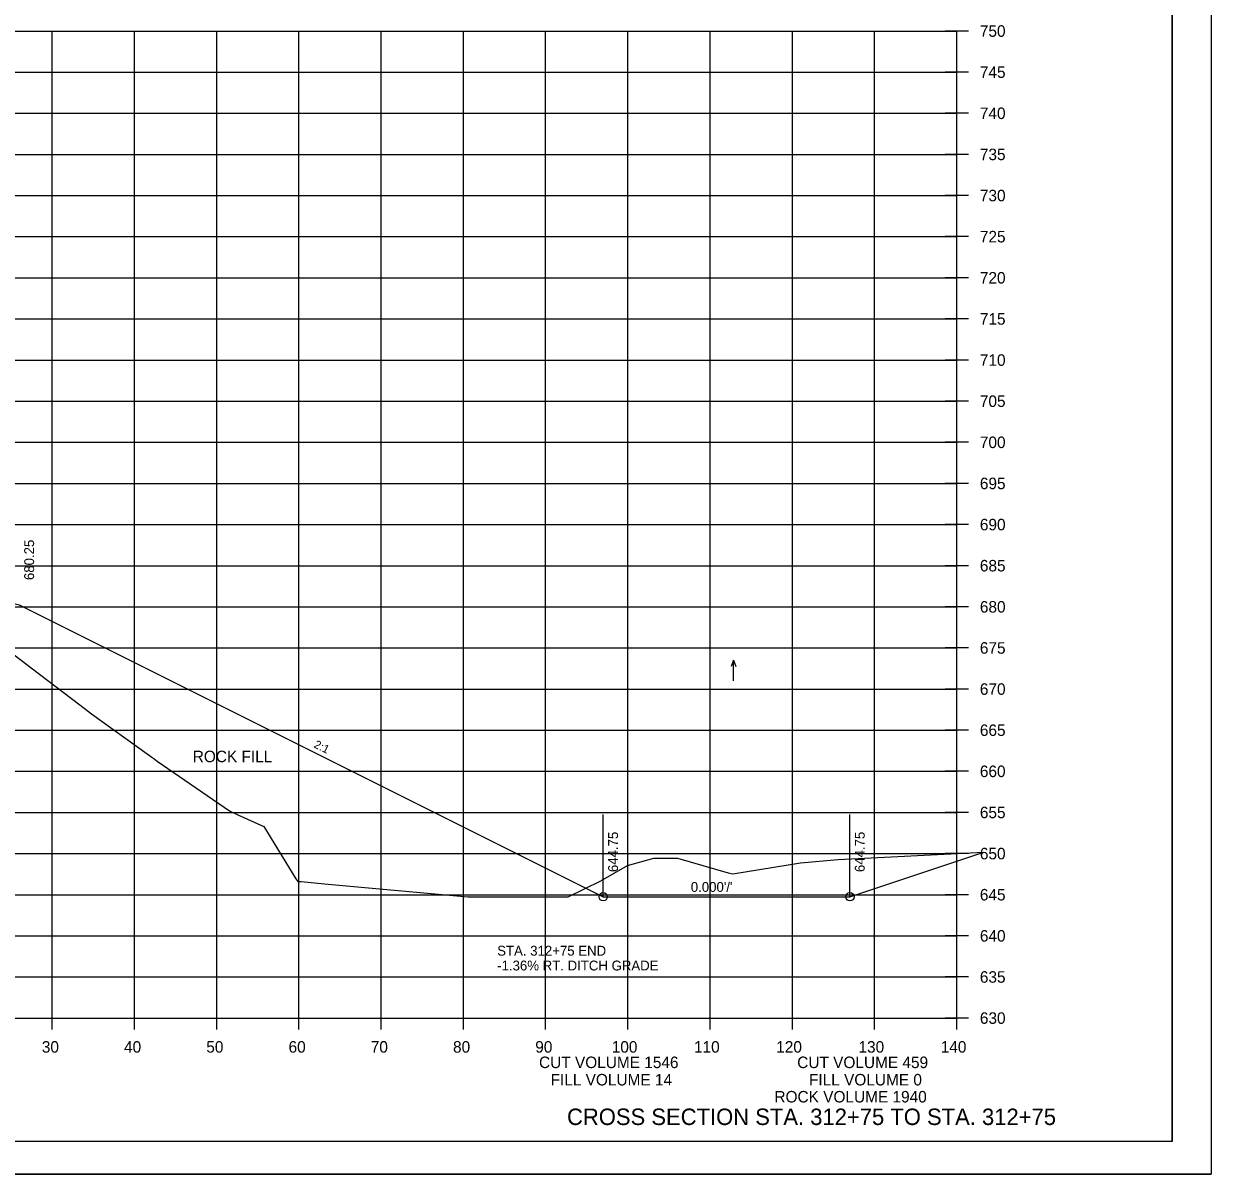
# Model space of a CAD drawing. Extents: x 1370515 to 1370849, y 383299 to 386073.
# Drawn here: x 1370704.3 to 1370848.7, y 385432.8 to 385572.7 of the extents above; entities that cross this region are included whole.
import ezdxf

# ---------------------------------------------------------------- set-up
doc = ezdxf.new("R2010")
doc.units = 0
for name, color, linetype in [('R_Axis', 7, 'Continuous'), ('R_Axis Annot', 7, 'Continuous'), ('R_Border', 7, 'Continuous'), ('R_Draft', 7, 'Continuous'), ('R_Drive', 7, 'Continuous'), ('R_Exist Surface', 7, 'Continuous'), ('R_Fin Surface', 7, 'Continuous'), ('R_Grid', 7, 'Continuous'), ('R_No Plot', 7, 'Continuous'), ('R_Water Annot', 7, 'Continuous'), ('R_Xsect Elev', 7, 'Continuous'), ('R_Xsect Slope', 7, 'Continuous')]:
    doc.layers.add(name, color=color, linetype=linetype)

msp = doc.modelspace()

# ---------------------------------------------------------------- linework, layer by layer
at = {"layer": 'R_Axis'}
for p, q in [((1370819.2, 385571.79), (1370816.4, 385571.79)), ((1370817.8, 385451.79), (1370817.8, 385571.79)), ((1370819.2, 385566.79), (1370816.4, 385566.79)), ((1370819.2, 385561.79), (1370816.4, 385561.79)), ((1370819.2, 385556.79), (1370816.4, 385556.79)), ((1370819.2, 385551.79), (1370816.4, 385551.79)), ((1370819.2, 385546.79), (1370816.4, 385546.79)), ((1370819.2, 385541.79), (1370816.4, 385541.79)), ((1370819.2, 385536.79), (1370816.4, 385536.79)), ((1370819.2, 385531.79), (1370816.4, 385531.79)), ((1370819.2, 385526.79), (1370816.4, 385526.79)), ((1370819.2, 385521.79), (1370816.4, 385521.79)), ((1370819.2, 385516.79), (1370816.4, 385516.79)), ((1370819.2, 385511.79), (1370816.4, 385511.79)), ((1370819.2, 385506.79), (1370816.4, 385506.79)), ((1370819.2, 385501.79), (1370816.4, 385501.79)), ((1370819.2, 385496.79), (1370816.4, 385496.79)), ((1370819.2, 385491.79), (1370816.4, 385491.79)), ((1370819.2, 385486.79), (1370816.4, 385486.79)), ((1370819.2, 385481.79), (1370816.4, 385481.79)), ((1370819.2, 385476.79), (1370816.4, 385476.79)), ((1370819.2, 385471.79), (1370816.4, 385471.79)), ((1370819.2, 385466.79), (1370816.4, 385466.79)), ((1370819.2, 385461.79), (1370816.4, 385461.79)), ((1370819.2, 385456.79), (1370816.4, 385456.79)), ((1370707.8, 385450.39), (1370707.8, 385453.19)), ((1370717.8, 385450.39), (1370717.8, 385453.19)), ((1370727.8, 385450.39), (1370727.8, 385453.19)), ((1370737.8, 385450.39), (1370737.8, 385453.19)), ((1370747.8, 385450.39), (1370747.8, 385453.19)), ((1370757.8, 385450.39), (1370757.8, 385453.19)), ((1370767.8, 385450.39), (1370767.8, 385453.19)), ((1370777.8, 385450.39), (1370777.8, 385453.19)), ((1370787.8, 385450.39), (1370787.8, 385453.19)), ((1370797.8, 385450.39), (1370797.8, 385453.19)), ((1370807.8, 385450.39), (1370807.8, 385453.19)), ((1370817.8, 385450.39), (1370817.8, 385453.19)), ((1370537.8, 385451.79), (1370817.8, 385451.79)), ((1370819.2, 385451.79), (1370816.4, 385451.79))]:
    msp.add_line(p, q, dxfattribs=at)
at = {"layer": 'R_Border'}
for q in [(1370843.98, 385642.25), (1370527.8, 385436.79)]:
    msp.add_line((1370843.98, 385436.79), q, dxfattribs=at)
at = {"layer": 'R_Exist Surface'}
msp.add_lwpolyline([(1370695.72, 385501.64), (1370705.26, 385494.38), (1370711.15, 385489.86), (1370712.6, 385488.77), (1370719.33, 385483.93), (1370719.92, 385483.5), (1370720.01, 385483.43), (1370720.16, 385483.33), (1370720.58, 385483.04), (1370729.35, 385476.99), (1370730.39, 385476.52), (1370733.54, 385475.07), (1370737.44, 385468.73), (1370737.67, 385468.41), (1370738.06, 385468.38), (1370740.92, 385468.12), (1370758.36, 385466.53), (1370760.29, 385466.54), (1370770.53, 385466.54), (1370774.53, 385468.49), (1370777.75, 385470.33), (1370780.95, 385471.22), (1370783.83, 385471.25), (1370790, 385469.46), (1370790.58, 385469.31), (1370798.77, 385470.65), (1370803.35, 385471.09), (1370821.08, 385471.96)], dxfattribs=at)
at = {"layer": 'R_Fin Surface'}
msp.add_lwpolyline([(1370554.83, 385551.11), (1370629.47, 385513.79), (1370634.47, 385513.79), (1370637.83, 385500.34), (1370647.83, 385500.34), (1370651.8, 385501.66), (1370652.52, 385501.84), (1370657.8, 385503.16), (1370665.8, 385503.48), (1370677.8, 385503.72), (1370689.8, 385503.61), (1370697.8, 385503.54), (1370703.8, 385502.04), (1370774.8, 385466.54), (1370804.8, 385466.54), (1370821.08, 385471.96)], dxfattribs=at)
at = {"layer": 'R_Grid'}
for p, q in [((1370537.8, 385571.79), (1370817.8, 385571.79)), ((1370707.8, 385451.79), (1370707.8, 385571.79)), ((1370717.8, 385451.79), (1370717.8, 385571.79)), ((1370727.8, 385451.79), (1370727.8, 385571.79)), ((1370737.8, 385451.79), (1370737.8, 385571.79)), ((1370747.8, 385451.79), (1370747.8, 385571.79)), ((1370757.8, 385451.79), (1370757.8, 385571.79)), ((1370767.8, 385451.79), (1370767.8, 385571.79)), ((1370777.8, 385451.79), (1370777.8, 385571.79)), ((1370787.8, 385451.79), (1370787.8, 385571.79)), ((1370797.8, 385451.79), (1370797.8, 385571.79)), ((1370807.8, 385451.79), (1370807.8, 385571.79)), ((1370817.8, 385451.79), (1370817.8, 385571.79)), ((1370537.8, 385566.79), (1370817.8, 385566.79)), ((1370537.8, 385561.79), (1370817.8, 385561.79)), ((1370537.8, 385556.79), (1370817.8, 385556.79)), ((1370537.8, 385551.79), (1370817.8, 385551.79)), ((1370537.8, 385546.79), (1370817.8, 385546.79)), ((1370537.8, 385541.79), (1370817.8, 385541.79)), ((1370537.8, 385536.79), (1370817.8, 385536.79)), ((1370537.8, 385531.79), (1370817.8, 385531.79)), ((1370537.8, 385526.79), (1370817.8, 385526.79)), ((1370537.8, 385521.79), (1370817.8, 385521.79)), ((1370537.8, 385516.79), (1370817.8, 385516.79)), ((1370537.8, 385511.79), (1370817.8, 385511.79)), ((1370537.8, 385506.79), (1370817.8, 385506.79)), ((1370537.8, 385501.79), (1370817.8, 385501.79)), ((1370537.8, 385496.79), (1370817.8, 385496.79)), ((1370537.8, 385491.79), (1370817.8, 385491.79)), ((1370537.8, 385486.79), (1370817.8, 385486.79)), ((1370537.8, 385481.79), (1370817.8, 385481.79)), ((1370537.8, 385476.79), (1370817.8, 385476.79)), ((1370537.8, 385471.79), (1370817.8, 385471.79)), ((1370537.8, 385466.79), (1370817.8, 385466.79)), ((1370537.8, 385461.79), (1370817.8, 385461.79)), ((1370537.8, 385456.79), (1370817.8, 385456.79)), ((1370537.8, 385451.79), (1370817.8, 385451.79))]:
    msp.add_line(p, q, dxfattribs=at)
at = {"layer": 'R_No Plot'}
msp.add_line((1370515.4, 385432.81), (1370848.73, 385432.81), dxfattribs=at)
for points in [[(1370515.39, 385646.14), (1370848.73, 385646.14), (1370848.73, 385432.81), (1370515.39, 385432.81)], [(1370761.72, 385642.25), (1370761.72, 385632.37), (1370797.45, 385632.37), (1370797.45, 385629.45), (1370820.65, 385629.45), (1370820.65, 385606.23), (1370843.98, 385606.23), (1370843.98, 385436.79), (1370527.8, 385436.79), (1370527.8, 385642.25)]]:
    msp.add_lwpolyline(points, close=True, dxfattribs=at)
for centre in [(1370774.8, 385466.54), (1370774.8, 385466.54), (1370804.8, 385466.54)]:
    msp.add_circle(centre, 0.5, dxfattribs=at)
at = {"layer": 'R_Water Annot'}
for p, q in [((1370790.65, 385495.32), (1370790.37, 385494.55)), ((1370790.65, 385492.8), (1370790.65, 385495.32)), ((1370790.65, 385495.32), (1370790.93, 385494.55))]:
    msp.add_line(p, q, dxfattribs=at)
at = {"layer": 'R_Xsect Elev'}
for p, q in [((1370774.8, 385466.54), (1370774.8, 385476.54)), ((1370804.8, 385466.54), (1370804.8, 385476.54))]:
    msp.add_line(p, q, dxfattribs=at)

# ---------------------------------------------------------------- texts
at = {"layer": 'R_Axis Annot'}
for s, p in [('750', (1370820.6, 385571.09)), ('745', (1370820.6, 385566.09)), ('740', (1370820.6, 385561.09)), ('735', (1370820.6, 385556.09)), ('730', (1370820.6, 385551.09)), ('725', (1370820.6, 385546.09)), ('720', (1370820.6, 385541.09)), ('715', (1370820.6, 385536.09)), ('710', (1370820.6, 385531.09)), ('705', (1370820.6, 385526.09)), ('700', (1370820.6, 385521.09)), ('695', (1370820.6, 385516.09)), ('690', (1370820.6, 385511.09)), ('685', (1370820.6, 385506.09)), ('680', (1370820.6, 385501.09)), ('675', (1370820.6, 385496.09)), ('670', (1370820.6, 385491.09)), ('665', (1370820.6, 385486.09)), ('ROCK FILL', (1370724.89, 385482.9)), ('660', (1370820.6, 385481.09)), ('655', (1370820.6, 385476.09)), ('650', (1370820.6, 385471.09)), ('645', (1370820.6, 385466.09)), ('640', (1370820.6, 385461.09)), ('635', (1370820.6, 385456.09)), ('630', (1370820.6, 385451.09)), ('30', (1370706.54, 385447.59)), ('40', (1370716.54, 385447.59)), ('50', (1370726.54, 385447.59)), ('60', (1370736.54, 385447.59)), ('70', (1370746.54, 385447.59)), ('80', (1370756.54, 385447.59)), ('90', (1370766.54, 385447.59)), ('100', (1370775.84, 385447.59)), ('110', (1370785.84, 385447.59)), ('120', (1370795.84, 385447.59)), ('130', (1370805.84, 385447.59)), ('140', (1370815.84, 385447.59)), ('CUT VOLUME 1546', (1370767, 385445.71)), ('CUT VOLUME 459', (1370798.39, 385445.71)), ('FILL VOLUME 14', (1370768.4, 385443.6)), ('FILL VOLUME 0', (1370799.82, 385443.6)), ('ROCK VOLUME 1940', (1370795.62, 385441.53))]:
    msp.add_text(s, height=1.4, dxfattribs=at).set_placement(p)
at = {"layer": 'R_Draft'}
msp.add_text('CROSS SECTION STA. 312+75 TO STA. 312+75', height=2, dxfattribs=at).set_placement((1370770.4, 385438.79))
at = {"layer": 'R_Drive'}
for s, p in [('STA. 312+75 END', (1370761.91, 385459.38)), ('-1.36% RT. DITCH GRADE', (1370761.91, 385457.58))]:
    msp.add_text(s, height=1.2, dxfattribs=at).set_placement(p)
at = {"layer": 'R_No Plot'}
for p in [(1370705.21, 385494.33), (1370712.55, 385488.72), (1370719.97, 385483.38), (1370729.31, 385476.94), (1370733.49, 385475.02), (1370777.71, 385470.28), (1370783.79, 385471.2), (1370790.54, 385469.26), (1370737.63, 385468.36), (1370758.31, 385466.48), (1370770.49, 385466.49)]:
    msp.add_text('+', height=0.1, dxfattribs=at).set_placement(p)
at = {"layer": 'R_Xsect Elev'}
for s, p in [('680.25', (1370705.6, 385505.04)), ('644.75', (1370776.6, 385469.54)), ('644.75', (1370806.6, 385469.54))]:
    msp.add_text(s, height=1.2, rotation=90, dxfattribs=at).set_placement(p)
at = {"layer": 'R_Xsect Slope'}
msp.add_text('2:1', height=1, rotation=333.4349, dxfattribs=at).set_placement((1370739.53, 385484.74))
msp.add_text("0.000'/'", height=1.2, dxfattribs=at).set_placement((1370785.45, 385467.13))

doc.saveas('drawing.dxf')
